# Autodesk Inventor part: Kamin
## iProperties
Created: 2007-03
Part Number: Kamin
Document SubType Name: Modeling
Designer: Benno
Manufacturer: Standard
Standards Organization: Custom
Author: Benno
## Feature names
1. Drehung1 [Revolution]
2. Bohrung1 [Hole]
3. Fase1 [Chamfer]
